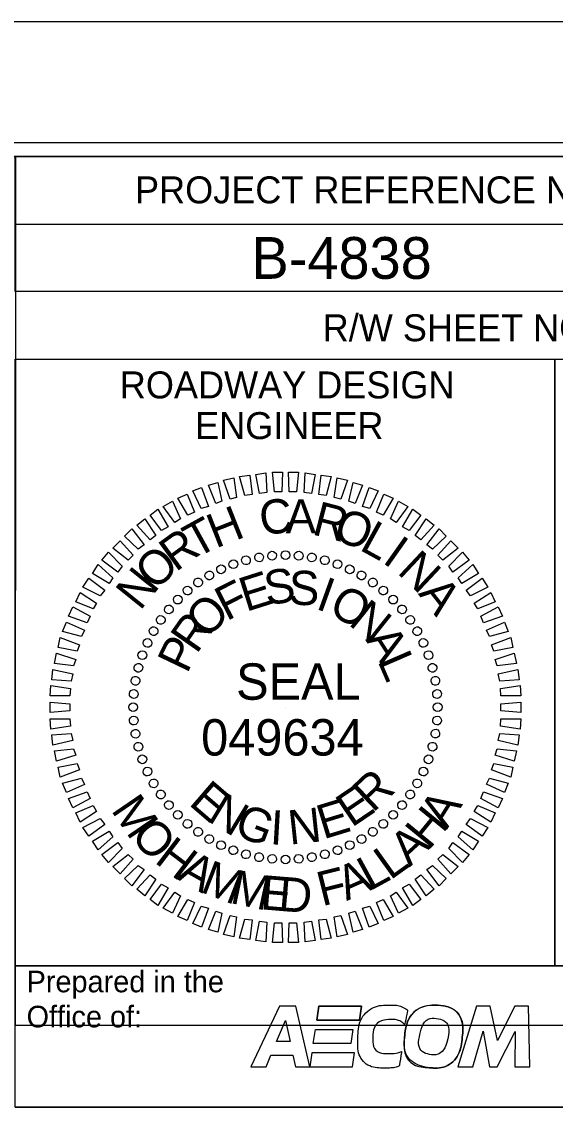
# Model space of a CAD drawing. Extents: x -130 to 890, y -29895 to -29235.
# Drawn here: x 750.7 to 810, y -29355.5 to -29234.8 of the extents above; entities that cross this region are included whole.
import ezdxf

# ---------------------------------------------------------------- set-up
doc = ezdxf.new("R2010")
doc.units = 0
for name, color, linetype in [('Default', 7, 'Continuous'), ('Prop DSN Text', 7, 'Continuous'), ('Scratch_Level_0', 7, 'Continuous'), ('Sheet Block Title CELL', 7, 'Continuous'), ('Sheet Border Standard 30in CELL', 7, 'Continuous'), ('Sheet Cutting Line CELL', 7, 'Continuous'), ('Sheet Data Field CELL', 7, 'Continuous'), ('Sheet Plot Border Inside CELL', 7, 'Continuous'), ('Sheet Plot Border Outside CELL', 7, 'Continuous'), ('Sheet Professional Seal CELL', 7, 'Continuous'), ('Sheet Profile CELL', 7, 'Continuous'), ('Sheet Sticker Exception Certification CELL', 7, 'Continuous')]:
    doc.layers.add(name, color=color, linetype=linetype)

# ---------------------------------------------------------------- blocks, each defined once
blk = doc.blocks.new('block 3')
at = {"layer": 'Default'}
blk.add_open_spline([(0.12275, 0.09393), (0.12554, 0.09373), (0.12726, 0.09146), (0.12695, 0.08843), (0.12663, 0.08531), (0.12411, 0.08298), (0.12127, 0.08318), (0.11848, 0.08338), (0.11676, 0.08565), (0.11707, 0.08868), (0.11739, 0.0918), (0.11991, 0.09413), (0.12275, 0.09393)], degree=3, dxfattribs=at)
blk = doc.blocks.new('block 2')
at = {"layer": 'Default'}
for p, q in [((0.10234, 0.09375), (0.10197, 0.09133)), ((0.10966, 0.09375), (0.10234, 0.09375)), ((0.10929, 0.09133), (0.10966, 0.09375)), ((0.10137, 0.08733), (0.10174, 0.08975)), ((0.10174, 0.08975), (0.10818, 0.08975)), ((0.10197, 0.09133), (0.10929, 0.09133)), ((0.10818, 0.08975), (0.10782, 0.08733)), ((0.10114, 0.08576), (0.10078, 0.08333)), ((0.10846, 0.08576), (0.10114, 0.08576)), ((0.10782, 0.08733), (0.10137, 0.08733)), ((0.1081, 0.08333), (0.10846, 0.08576)), ((0.10078, 0.08333), (0.1081, 0.08333))]:
    blk.add_line(p, q, dxfattribs=at)
for points in [[(0.10929, 0.09133), (0.10197, 0.09133), (0.10234, 0.09375), (0.10966, 0.09375), (0.10929, 0.09133)], [(0.10782, 0.08733), (0.10137, 0.08733), (0.10174, 0.08975), (0.10818, 0.08975), (0.10782, 0.08733)], [(0.10846, 0.08576), (0.10114, 0.08576), (0.10078, 0.08333), (0.1081, 0.08333), (0.10846, 0.08576)]]:
    blk.add_lwpolyline(points, dxfattribs=at)
blk = doc.blocks.new('POINT_DISPLAY')
at = {"layer": 'Default'}
blk.add_line((0, 0), (0, 0), dxfattribs=at)

msp = doc.modelspace()

# ---------------------------------------------------------------- linework, layer by layer
at = {"layer": 'Prop DSN Text'}
for p, q in [((779.35, -29344.29), (776.17, -29351.04)), ((781.18, -29344.29), (779.35, -29344.29)), ((782.74, -29351.04), (781.18, -29344.29)), ((801.29, -29344.29), (799.2, -29351.04)), ((802.81, -29344.29), (801.29, -29344.29)), ((803.6, -29348.09), (802.81, -29344.29)), ((805.55, -29344.29), (803.6, -29348.09)), ((807.07, -29344.29), (805.55, -29344.29)), ((807.19, -29351.04), (807.07, -29344.29)), ((779.04, -29348.23), (780.02, -29345.89)), ((780.02, -29345.89), (780.04, -29345.89)), ((780.04, -29345.89), (780.54, -29348.23)), ((800.87, -29351.04), (802.02, -29347.08)), ((802.02, -29347.08), (802.73, -29351.04)), ((803.59, -29351.04), (805.57, -29347.09)), ((805.57, -29347.09), (805.54, -29351.04)), ((780.54, -29348.23), (779.04, -29348.23)), ((777.87, -29351.04), (778.42, -29349.72)), ((778.42, -29349.72), (780.85, -29349.72)), ((780.85, -29349.72), (781.13, -29351.04)), ((776.17, -29351.04), (777.87, -29351.04)), ((781.13, -29351.04), (782.74, -29351.04)), ((799.2, -29351.04), (800.87, -29351.04)), ((802.73, -29351.04), (803.59, -29351.04)), ((805.54, -29351.04), (807.19, -29351.04))]:
    msp.add_line(p, q, dxfattribs=at)
for points in [[(781.13, -29351.04), (782.74, -29351.04), (781.18, -29344.29), (779.35, -29344.29), (776.17, -29351.04), (777.87, -29351.04), (778.42, -29349.72), (780.85, -29349.72), (781.13, -29351.04)], [(807.19, -29351.04), (807.07, -29344.29), (805.55, -29344.29), (803.6, -29348.09), (802.81, -29344.29), (801.29, -29344.29), (799.2, -29351.04), (800.87, -29351.04), (802.02, -29347.08), (802.73, -29351.04), (803.59, -29351.04), (805.57, -29347.09), (805.54, -29351.04), (807.19, -29351.04)]]:
    msp.add_lwpolyline(points, dxfattribs=at)
for points in [[(792.94, -29349.31), (792.49, -29349.52), (791.82, -29349.55), (791.48, -29349.55), (790.42, -29349.55), (789.71, -29348.82), (789.74, -29347.74), (789.78, -29346.59), (790.65, -29345.77), (791.82, -29345.77), (792.38, -29345.77), (792.86, -29345.96), (793.3, -29346.33), (793.3, -29346.33), (793.63, -29344.71), (793.63, -29344.71), (792.96, -29344.32), (792.39, -29344.16), (791.69, -29344.16), (789.75, -29344.16), (788.14, -29345.77), (788.08, -29347.81), (788.01, -29349.78), (789.29, -29351.17), (791.2, -29351.17), (791.53, -29351.17), (792.25, -29351.13), (792.7, -29350.93), (792.7, -29350.93), (792.94, -29349.31), (792.94, -29349.31)], [(792.94, -29349.31), (792.49, -29349.52), (791.82, -29349.55), (791.48, -29349.55), (790.42, -29349.55), (789.71, -29348.82), (789.74, -29347.74), (789.78, -29346.59), (790.65, -29345.77), (791.82, -29345.77), (792.38, -29345.77), (792.86, -29345.96), (793.3, -29346.33), (793.3, -29346.33), (793.63, -29344.71), (793.63, -29344.71), (792.96, -29344.32), (792.39, -29344.16), (791.69, -29344.16), (789.75, -29344.16), (788.14, -29345.77), (788.08, -29347.81), (788.01, -29349.78), (789.29, -29351.17), (791.2, -29351.17), (791.53, -29351.17), (792.25, -29351.13), (792.7, -29350.93), (792.7, -29350.93), (792.94, -29349.31), (792.94, -29349.31)], [(795.31, -29351.01), (793.93, -29350.59), (793.12, -29349.27), (793.29, -29347.57), (793.5, -29345.55), (795.14, -29344.04), (796.98, -29344.17)], [(796.98, -29344.17), (798.78, -29344.3), (799.9, -29345.77), (799.7, -29347.73), (799.49, -29349.76), (797.86, -29351.27), (796.01, -29351.13), (795.77, -29351.12), (795.53, -29351.07), (795.31, -29351.01)], [(798.09, -29347.9), (798.34, -29346.76), (797.91, -29345.87), (797.05, -29345.69), (796.1, -29345.5), (795.24, -29346.22), (794.98, -29347.43), (794.73, -29348.57), (795.16, -29349.46), (796.02, -29349.64), (796.97, -29349.83), (797.83, -29349.1), (798.09, -29347.9)], [(798.09, -29347.9), (798.34, -29346.76), (797.91, -29345.87), (797.05, -29345.69), (796.1, -29345.5), (795.24, -29346.22), (794.98, -29347.43), (794.73, -29348.57), (795.16, -29349.46), (796.02, -29349.64), (796.97, -29349.83), (797.83, -29349.1), (798.09, -29347.9)]]:
    msp.add_open_spline(points, degree=3, dxfattribs=at)
at = {"layer": 'Scratch_Level_0'}
msp.add_lwpolyline([(450, -29249.75), (750, -29249.75), (749.97, -29346.38), (840, -29346.38), (840, -29549.75), (450, -29549.75)], close=True, dxfattribs=at)
at = {"layer": 'Sheet Block Title CELL'}
msp.add_lwpolyline([(749.97, -29339.78), (869.97, -29339.78), (869.97, -29355.53), (749.97, -29355.53)], close=True, dxfattribs=at)
at = {"layer": 'Sheet Border Standard 30in CELL'}
for points in [[(749.97, -29272.28), (810, -29272.28), (810, -29339.78), (749.97, -29339.78)], [(810, -29272.28), (870, -29272.28), (870, -29339.78), (810, -29339.78)]]:
    msp.add_lwpolyline(points, close=True, dxfattribs=at)
at = {"layer": 'Sheet Cutting Line CELL'}
msp.add_line((889.8, -29234.75), (-130.2, -29234.75), dxfattribs=at)
at = {"layer": 'Sheet Plot Border Inside CELL'}
msp.add_lwpolyline([(-122.4, -29881.28), (877.5, -29881.28), (877.5, -29248.22), (-122.4, -29248.22)], close=True, dxfattribs=at)
at = {"layer": 'Sheet Plot Border Outside CELL'}
msp.add_lwpolyline([(-130.2, -29894.75), (889.8, -29894.75), (889.8, -29234.75), (-130.2, -29234.75)], close=True, dxfattribs=at)
at = {"layer": 'Sheet Professional Seal CELL'}
for points in [[(777.13, -29287.23), (776.72, -29285.11), (777.84, -29284.94), (777.94, -29287.13)], [(778.81, -29287.06), (778.58, -29284.87), (779.69, -29284.87), (779.62, -29287.06)], [(780.44, -29287.06), (780.37, -29284.87), (781.48, -29284.87), (781.24, -29287.06)], [(782.12, -29287.13), (782.22, -29284.94), (783.34, -29285.11), (782.93, -29287.23)], [(772.27, -29288.35), (771.46, -29286.32), (772.5, -29286.02), (772.97, -29288.11)], [(773.89, -29287.87), (773.14, -29285.75), (774.29, -29285.51), (774.59, -29287.7)], [(775.51, -29287.47), (774.93, -29285.34), (776.05, -29285.21), (776.32, -29287.37)], [(783.74, -29287.37), (784.01, -29285.21), (785.13, -29285.34), (784.55, -29287.47)], [(785.46, -29287.7), (785.77, -29285.51), (786.92, -29285.75), (786.17, -29287.87)], [(787.08, -29288.11), (787.56, -29286.02), (788.6, -29286.32), (787.79, -29288.35)], [(769.16, -29289.66), (768.05, -29287.77), (769.09, -29287.3), (769.9, -29289.33)], [(770.65, -29288.92), (769.73, -29286.96), (770.71, -29286.56), (771.46, -29288.68)], [(788.6, -29288.68), (789.35, -29286.56), (790.33, -29286.96), (789.41, -29288.92)], [(790.16, -29289.33), (790.97, -29287.3), (792.01, -29287.77), (790.9, -29289.66)], [(767.71, -29290.47), (766.43, -29288.68), (767.47, -29288.11), (768.35, -29290.07)], [(791.71, -29290.07), (792.59, -29288.11), (793.63, -29288.68), (792.35, -29290.47)], [(766.26, -29291.35), (764.97, -29289.66), (765.85, -29288.99), (767, -29290.95)], [(793.06, -29290.95), (794.21, -29288.99), (795.08, -29289.66), (793.8, -29291.35)], [(764.97, -29292.4), (763.49, -29290.78), (764.4, -29290.07), (765.62, -29291.92)], [(794.44, -29291.92), (795.66, -29290.07), (796.57, -29290.78), (795.08, -29292.4)], [(763.66, -29293.44), (762.14, -29291.99), (762.95, -29291.18), (764.3, -29292.97)], [(795.76, -29292.97), (797.11, -29291.18), (797.92, -29291.99), (796.4, -29293.44)], [(762.54, -29294.66), (760.82, -29293.31), (761.63, -29292.5), (763.08, -29294.12)], [(796.98, -29294.12), (798.43, -29292.5), (799.24, -29293.31), (797.52, -29294.66)], [(761.4, -29295.98), (759.61, -29294.66), (760.35, -29293.78), (761.87, -29295.33)], [(798.19, -29295.33), (799.71, -29293.78), (800.45, -29294.66), (798.66, -29295.98)], [(760.42, -29297.26), (758.56, -29296.14), (759.2, -29295.16), (760.82, -29296.62)], [(799.24, -29296.62), (800.86, -29295.16), (801.5, -29296.14), (799.64, -29297.26)], [(759.44, -29298.64), (757.51, -29297.66), (758.16, -29296.68), (759.94, -29298)], [(800.12, -29298), (801.9, -29296.68), (802.55, -29297.66), (800.62, -29298.64)], [(758.63, -29300.09), (756.7, -29299.28), (757.18, -29298.24), (759.03, -29299.45)], [(801.03, -29299.45), (802.88, -29298.24), (803.36, -29299.28), (801.43, -29300.09)], [(757.99, -29301.65), (755.89, -29300.9), (756.37, -29299.86), (758.32, -29300.9)], [(801.74, -29300.9), (803.69, -29299.86), (804.17, -29300.9), (802.07, -29301.65)], [(757.35, -29303.17), (755.25, -29302.59), (755.66, -29301.55), (757.68, -29302.46)], [(802.38, -29302.46), (804.4, -29301.54), (804.81, -29302.59), (802.71, -29303.17)], [(756.87, -29304.79), (754.75, -29304.38), (754.98, -29303.27), (757.11, -29304.08)], [(802.95, -29304.08), (805.08, -29303.27), (805.31, -29304.38), (803.19, -29304.78)], [(756.47, -29306.41), (754.34, -29306.17), (754.58, -29305.02), (756.7, -29305.7)], [(803.36, -29305.7), (805.48, -29305.02), (805.72, -29306.17), (803.59, -29306.41)], [(756.2, -29308.13), (754.04, -29307.96), (754.17, -29306.81), (756.37, -29307.32)], [(803.69, -29307.32), (805.89, -29306.81), (806.02, -29307.96), (803.86, -29308.13)], [(756.06, -29309.75), (753.87, -29309.75), (753.94, -29308.6), (756.13, -29308.94)], [(803.93, -29308.94), (806.12, -29308.6), (806.19, -29309.75), (804, -29309.75)], [(756.06, -29311.44), (753.87, -29311.6), (753.87, -29310.46), (756.06, -29310.63)], [(804, -29310.63), (806.19, -29310.46), (806.19, -29311.6), (804, -29311.44)], [(756.13, -29313.12), (753.94, -29313.46), (753.87, -29312.31), (756.06, -29312.31)], [(804, -29312.31), (806.19, -29312.31), (806.12, -29313.46), (803.93, -29313.12)], [(756.37, -29314.74), (754.17, -29315.25), (754.04, -29314.1), (756.2, -29313.93)], [(803.86, -29313.93), (806.02, -29314.1), (805.89, -29315.25), (803.69, -29314.74)], [(756.7, -29316.36), (754.58, -29317.04), (754.34, -29315.89), (756.47, -29315.66)], [(803.59, -29315.65), (805.72, -29315.89), (805.48, -29317.04), (803.36, -29316.36)], [(757.11, -29317.98), (754.98, -29318.79), (754.75, -29317.68), (756.87, -29317.28)], [(803.19, -29317.28), (805.31, -29317.68), (805.08, -29318.79), (802.95, -29317.98)], [(757.68, -29319.61), (755.66, -29320.52), (755.25, -29319.47), (757.35, -29318.9)], [(802.71, -29318.9), (804.81, -29319.47), (804.4, -29320.52), (802.38, -29319.6)], [(758.32, -29321.16), (756.37, -29322.2), (755.89, -29321.16), (757.99, -29320.42)], [(802.07, -29320.42), (804.17, -29321.16), (803.69, -29322.2), (801.74, -29321.16)], [(759.03, -29322.61), (757.18, -29323.82), (756.7, -29322.78), (758.63, -29321.97)], [(801.43, -29321.97), (803.36, -29322.78), (802.88, -29323.82), (801.03, -29322.61)], [(759.95, -29324.06), (758.16, -29325.38), (757.51, -29324.4), (759.44, -29323.42)], [(800.62, -29323.42), (802.55, -29324.4), (801.9, -29325.38), (800.12, -29324.06)], [(760.82, -29325.44), (759.2, -29326.9), (758.56, -29325.92), (760.42, -29324.8)], [(799.64, -29324.8), (801.5, -29325.92), (800.86, -29326.9), (799.24, -29325.44)], [(761.87, -29326.73), (760.35, -29328.28), (759.61, -29327.4), (761.4, -29326.09)], [(798.66, -29326.09), (800.45, -29327.4), (799.71, -29328.28), (798.19, -29326.73)], [(763.08, -29327.94), (761.63, -29329.56), (760.82, -29328.75), (762.54, -29327.4)], [(797.52, -29327.4), (799.24, -29328.75), (798.43, -29329.56), (796.98, -29327.94)], [(764.3, -29329.09), (762.95, -29330.88), (762.14, -29330.07), (763.66, -29328.62)], [(765.62, -29330.14), (764.4, -29331.99), (763.49, -29331.28), (764.97, -29329.66)], [(795.09, -29329.66), (796.57, -29331.28), (795.66, -29331.99), (794.44, -29330.14)], [(796.4, -29328.62), (797.92, -29330.07), (797.11, -29330.88), (795.76, -29329.09)], [(767, -29331.12), (765.85, -29333.07), (764.97, -29332.4), (766.26, -29330.71)], [(793.8, -29330.71), (795.09, -29332.4), (794.21, -29333.07), (793.06, -29331.12)], [(768.35, -29331.99), (767.47, -29333.95), (766.43, -29333.38), (767.71, -29331.59)], [(792.35, -29331.59), (793.63, -29333.38), (792.59, -29333.95), (791.71, -29331.99)], [(769.9, -29332.74), (769.09, -29334.76), (768.05, -29334.29), (769.16, -29332.4)], [(771.46, -29333.38), (770.71, -29335.5), (769.73, -29335.1), (770.65, -29333.14)], [(789.41, -29333.14), (790.33, -29335.1), (789.35, -29335.5), (788.6, -29333.38)], [(790.9, -29332.4), (792.01, -29334.29), (790.97, -29334.76), (790.16, -29332.74)], [(772.97, -29333.95), (772.5, -29336.04), (771.46, -29335.74), (772.27, -29333.71)], [(774.59, -29334.36), (774.29, -29336.55), (773.14, -29336.31), (773.89, -29334.19)], [(776.32, -29334.69), (776.05, -29336.85), (774.93, -29336.72), (775.51, -29334.59)], [(784.55, -29334.59), (785.13, -29336.72), (784.01, -29336.85), (783.74, -29334.69)], [(786.17, -29334.19), (786.92, -29336.31), (785.77, -29336.55), (785.46, -29334.36)], [(787.79, -29333.71), (788.6, -29335.74), (787.56, -29336.04), (787.08, -29333.95)], [(777.94, -29334.93), (777.84, -29337.13), (776.72, -29336.96), (777.13, -29334.83)], [(779.63, -29335), (779.69, -29337.19), (778.58, -29337.19), (778.81, -29335)], [(781.24, -29335), (781.48, -29337.19), (780.37, -29337.19), (780.44, -29335)], [(782.93, -29334.83), (783.34, -29336.96), (782.22, -29337.12), (782.12, -29334.93)]]:
    msp.add_lwpolyline(points, close=True, dxfattribs=at)
for centre, major_axis in [((774.23, -29295.11), (-0.166, 0.457)), ((775.64, -29294.67), (-0.126, 0.47)), ((777.09, -29294.35), (-0.084, 0.479)), ((778.55, -29294.16), (-0.042, 0.484)), ((780.03, -29294.09), (0, 0.486)), ((781.5, -29294.16), (0.042, 0.484)), ((782.97, -29294.35), (0.084, 0.479)), ((784.41, -29294.67), (0.126, 0.47)), ((785.82, -29295.11), (0.166, 0.457)), ((771.56, -29296.36), (-0.243, 0.421)), ((772.87, -29295.68), (-0.205, 0.441)), ((787.18, -29295.68), (0.205, 0.441)), ((788.49, -29296.36), (0.243, 0.421)), ((770.31, -29297.15), (-0.279, 0.398)), ((789.74, -29297.15), (0.279, 0.398)), ((769.14, -29298.05), (-0.312, 0.372)), ((790.91, -29298.05), (0.312, 0.372)), ((768.05, -29299.05), (-0.344, 0.344)), ((792, -29299.05), (0.344, 0.344)), ((766.16, -29301.31), (-0.398, 0.279)), ((767.06, -29300.14), (-0.372, 0.312)), ((793, -29300.14), (0.372, 0.312)), ((793.9, -29301.31), (0.398, 0.279)), ((765.36, -29302.56), (-0.421, 0.243)), ((794.69, -29302.56), (0.421, 0.243)), ((764.68, -29303.87), (-0.441, 0.205)), ((795.37, -29303.87), (0.441, 0.205)), ((764.11, -29305.23), (-0.457, 0.166)), ((795.94, -29305.23), (0.457, 0.166)), ((763.67, -29306.64), (-0.47, 0.126)), ((796.38, -29306.64), (0.47, 0.126)), ((763.35, -29308.08), (-0.479, 0.084)), ((796.7, -29308.08), (0.479, 0.084)), ((763.16, -29309.55), (-0.484, 0.042)), ((796.89, -29309.55), (0.484, 0.042)), ((763.09, -29311.02), (-0.486, 0)), ((796.96, -29311.02), (0.486, 0)), ((763.16, -29312.5), (-0.484, -0.042)), ((796.89, -29312.5), (0.484, -0.042)), ((763.35, -29313.97), (-0.479, -0.084)), ((796.7, -29313.96), (0.479, -0.084)), ((763.67, -29315.41), (-0.47, -0.126)), ((796.38, -29315.41), (0.47, -0.126)), ((764.11, -29316.82), (-0.457, -0.166)), ((795.94, -29316.82), (0.457, -0.166)), ((764.68, -29318.18), (-0.441, -0.205)), ((795.37, -29318.18), (0.441, -0.205)), ((765.36, -29319.49), (-0.421, -0.243)), ((794.69, -29319.49), (0.421, -0.243)), ((766.16, -29320.74), (-0.398, -0.279)), ((793.9, -29320.74), (0.398, -0.279)), ((767.06, -29321.91), (-0.372, -0.312)), ((768.05, -29323), (-0.344, -0.344)), ((792, -29323), (0.344, -0.344)), ((793, -29321.91), (0.372, -0.312)), ((769.14, -29324), (-0.312, -0.372)), ((790.91, -29324), (0.312, -0.372)), ((770.31, -29324.89), (-0.279, -0.398)), ((789.74, -29324.89), (0.279, -0.398)), ((771.56, -29325.69), (-0.243, -0.421)), ((772.87, -29326.37), (-0.205, -0.441)), ((787.18, -29326.37), (0.205, -0.441)), ((788.49, -29325.69), (0.243, -0.421)), ((774.23, -29326.94), (-0.166, -0.457)), ((775.64, -29327.38), (-0.126, -0.47)), ((777.09, -29327.7), (-0.084, -0.479)), ((782.97, -29327.7), (0.084, -0.479)), ((784.41, -29327.38), (0.126, -0.47)), ((785.82, -29326.94), (0.166, -0.457)), ((778.55, -29327.89), (-0.042, -0.484)), ((780.03, -29327.96), (0, -0.486)), ((781.5, -29327.89), (0.042, -0.484))]:
    msp.add_ellipse(centre, major_axis=major_axis, ratio=0.999708, dxfattribs=at)
at = {"layer": 'Sheet Profile CELL'}
msp.add_line((749.97, -29257.28), (870, -29257.28), dxfattribs=at)
for points in [[(870, -29249.75), (-30, -29249.75), (-30, -29879.75), (870, -29879.75)], [(749.97, -29249.75), (870, -29249.75), (870, -29264.78), (749.97, -29264.78)]]:
    msp.add_lwpolyline(points, close=True, dxfattribs=at)
at = {"layer": 'Sheet Sticker Exception Certification CELL'}
msp.add_line((749.97, -29355.53), (869.99, -29355.53), dxfattribs=at)

# ---------------------------------------------------------------- block references
at = {"layer": 'Prop DSN Text', "xscale": 648.001866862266, "yscale": 648.0018668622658, "rotation": 1.3379890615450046e-09}
for name in ['block 3', 'block 2']:
    msp.add_blockref(name, (717.43, -29405.04), dxfattribs=at)
at = {"layer": 'Sheet Professional Seal CELL', "xscale": 41.411959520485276, "yscale": 41.41195952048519, "rotation": 0.00042986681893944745}
for p in [(775.64, -29294.66), (777.09, -29294.36), (778.54, -29294.15), (780.03, -29294.09), (781.51, -29294.15), (782.97, -29294.36), (784.42, -29294.66), (772.87, -29295.67), (774.22, -29295.1), (785.84, -29295.1), (787.19, -29295.67), (770.31, -29297.16), (771.56, -29296.35), (788.5, -29296.35), (789.75, -29297.16), (769.13, -29298.03), (790.93, -29298.03), (768.05, -29299.05), (792.01, -29299.05), (767.03, -29300.13), (793.03, -29300.13), (766.16, -29301.31), (793.9, -29301.31), (765.35, -29302.56), (794.71, -29302.56), (764.67, -29303.87), (795.39, -29303.87), (764.1, -29305.23), (795.96, -29305.23), (763.66, -29306.64), (796.4, -29306.64), (763.35, -29308.09), (763.15, -29309.55), (796.91, -29309.55), (763.08, -29311.03), (780.03, -29311.03), (796.98, -29311.03), (763.15, -29312.52), (796.91, -29312.52), (763.35, -29313.97), (796.71, -29313.97), (763.66, -29315.42), (796.4, -29315.42), (764.1, -29316.84), (795.96, -29316.84), (795.39, -29318.19), (794.71, -29319.5), (766.16, -29320.75), (793.9, -29320.75), (767.03, -29321.93), (793.03, -29321.93), (768.05, -29323.01), (792.01, -29323.01), (769.13, -29324.03), (770.31, -29324.91), (789.75, -29324.9), (790.93, -29324.03), (771.56, -29325.71), (788.5, -29325.71), (772.87, -29326.39), (774.22, -29326.96), (785.84, -29326.96), (787.19, -29326.39), (775.64, -29327.4), (777.09, -29327.71), (778.54, -29327.91), (780.03, -29327.98), (781.51, -29327.91), (782.97, -29327.71), (784.42, -29327.4)]:
    msp.add_blockref('POINT_DISPLAY', p, dxfattribs=at)

# ---------------------------------------------------------------- texts
at = {"layer": 'Prop DSN Text'}
for s, p in [('Prepared in the ', (751.24, -29342.74)), ('Office of:', (751.24, -29346.64))]:
    msp.add_text(s, height=2.4, rotation=0, dxfattribs=at).set_placement(p)
at = {"layer": 'Sheet Border Standard 30in CELL'}
for s, height, p in [('R/W SHEET NO.', 3.0001, (784.17, -29270.3)), ('ROADWAY DESIGN', 3.0001, (761.61, -29276.66)), ('ENGINEER', 3, (769.98, -29281.19))]:
    msp.add_text(s, height=height, rotation=0, dxfattribs=at).set_placement(p)
at = {"layer": 'Sheet Data Field CELL'}
msp.add_text('B-4838', height=4.65, dxfattribs=at).set_placement((776.25, -29263.36))
at = {"layer": 'Sheet Professional Seal CELL'}
for s, height, rotation, p in [('H', 3.81, 21.6199, (772.27, -29293.38)), ('C', 3.81, 7.2203, (777.37, -29291.92)), ('A', 3.81, 0.0207, (780.04, -29291.69)), ('R', 3.81, 345.6215, (782.87, -29291.76)), ('T', 3.81, 28.8202, (770.07, -29294.52)), ('O', 3.81, 338.4216, (785.14, -29292.23)), ('L', 3.81, 331.2213, (788.14, -29293.45)), ('R', 3.81, 36.0209, (767.82, -29296.04)), ('I', 3.81, 324.781, (790.69, -29294.86)), ('O', 3.81, 43.2222, (765.52, -29298.16)), ('N', 3.81, 316.8193, (792.35, -29296.05)), ('N', 3.81, 51.1609, (763.86, -29300.37)), ('E', 3.81, 17.6115, (775.64, -29300.43)), ('S', 3.81, 8.256, (777.94, -29299.69)), ('S', 3.81, 358.9008, (780.37, -29299.62)), ('F', 3.81, 26.9675, (773.48, -29301.48)), ('I', 3.81, 340.19, (783.27, -29300.03)), ('O', 3.81, 330.8339, (784.66, -29300.5)), ('A', 3.81, 308.0625, (794.73, -29298.4)), ('O', 3.81, 45.6817, (771.29, -29303.5)), ('N', 3.81, 321.477, (786.92, -29301.78)), ('R', 3.81, 55.0401, (770.14, -29305.19)), ('P', 3.81, 64.3993, (769.09, -29307.38)), ('A', 3.81, 302.7607, (788.88, -29303.51)), ('L', 3.81, 293.4013, (790.23, -29305.84)), ('SEAL', 4.05, 0.0004, (774.54, -29310.19)), ('049634', 4.051, 0.0004, (770.65, -29316.4)), ('R', 3.81, 43.4818, (789.76, -29322.84)), ('E', 3.81, 319.2773, (769.16, -29321.8)), ('E', 3.81, 34.1245, (787.39, -29324.47)), ('M', 3.81, 304.4111, (760.56, -29322.47)), ('N', 3.81, 328.6344, (771.19, -29323.59)), ('E', 3.81, 16.9673, (784.24, -29325.74)), ('A', 3.81, 57.8787, (797.98, -29324.69)), ('G', 3.81, 339.5036, (774.16, -29325.2)), ('I', 3.81, 356.7016, (778.25, -29326.26)), ('N', 3.81, 6.0568, (780.51, -29326.32)), ('H', 3.81, 50.6835, (796.02, -29326.96)), ('O', 3.81, 313.5072, (762.68, -29325.51)), ('A', 3.81, 42.8793, (793.83, -29328.87)), ('H', 3.81, 322.6656, (765.35, -29328.23)), ('L', 3.81, 35.694, (791.68, -29330.32)), ('A', 3.81, 330.5496, (767.86, -29330.1)), ('M', 3.81, 338.9258, (770.43, -29331.52)), ('A', 3.81, 23.9839, (786.82, -29332.6)), ('L', 3.81, 28.7287, (789.42, -29331.5)), ('M', 3.81, 348.0168, (773.75, -29332.78)), ('E', 3.81, 355.1435, (777.18, -29333.49)), ('F', 3.81, 14.0832, (784.1, -29333.18)), ('D', 3.81, 355.1435, (779.17, -29333.65))]:
    msp.add_text(s, height=height, rotation=rotation, dxfattribs=at).set_placement(p)
at = {"layer": 'Sheet Profile CELL'}
msp.add_text('PROJECT REFERENCE NO.', height=3.0001, dxfattribs=at).set_placement((763.3, -29254.96))

doc.saveas('drawing.dxf')
